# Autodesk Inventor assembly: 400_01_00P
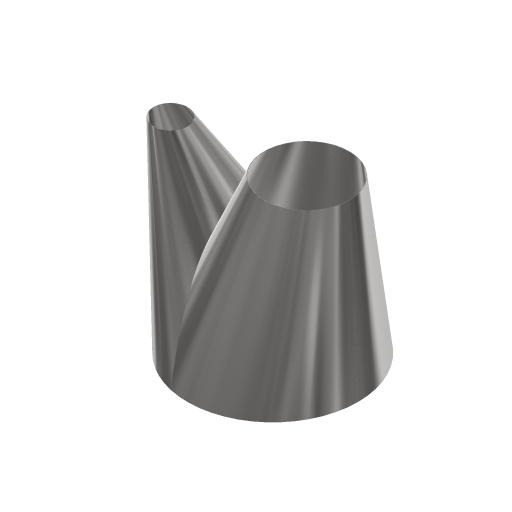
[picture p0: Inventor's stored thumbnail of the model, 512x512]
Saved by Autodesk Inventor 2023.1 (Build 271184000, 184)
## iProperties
Company: Fabian Stasiak CAD Consulting
Category: Autodesk® Inventor® Tutorial Series
Created: 2022-07
Part Number: 400_01_00P
Document SubType Name: Assembly
Designer: F.Stasiak
Description: Circular Duct Transition 250x50x125
Catalog Web Link: www.expertbooks.eu
Author: F.Stasiak
Subject: Sheet Metal Design. Basic and Advanced techniques
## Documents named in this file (3)
- C:\DesignOffice\Designs\SheetmetalDesign\400_01_00P.iam
- C:\DesignOffice\Designs\SheetmetalDesign\400_01_01P.ipt
- C:\DesignOffice\Designs\SheetmetalDesign\400_01_02P.ipt
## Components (2 placed, 2 different names)
1. 400_01_01P:1
2. 400_01_02P:1
